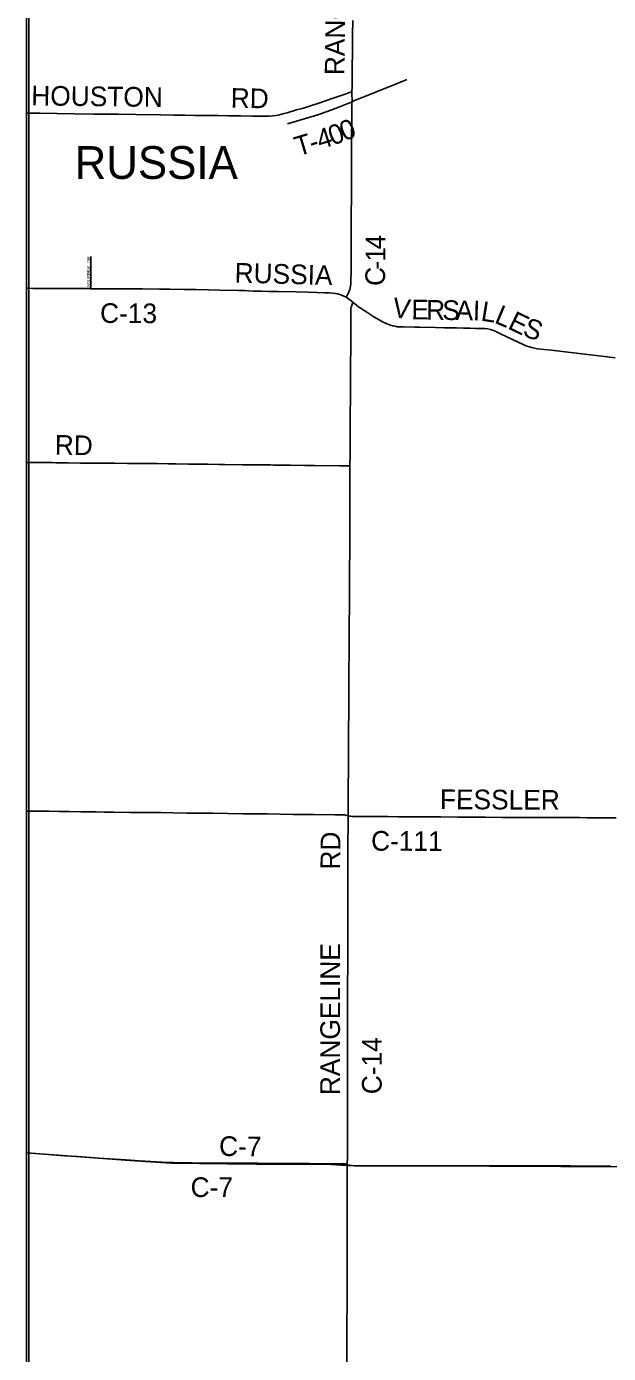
# Model space of a CAD drawing. Extents: x -87 to 2145, y -2128 to 440.
# Drawn here: x 90.3 to 134.7, y -467.2 to -365.9 of the extents above; entities that cross this region are included whole.
import ezdxf

# ---------------------------------------------------------------- set-up
doc = ezdxf.new("R2010")
doc.units = 0
for name, color, linetype in [('GM_X_Adjacent_County', 7, 'Continuous'), ('GM_X_City_Street', 7, 'Continuous'), ('GM_X_City_Street_Text', 7, 'Continuous'), ('GM_X_Corporation_Text', 7, 'Continuous'), ('GM_X_County', 7, 'Continuous'), ('GM_X_County_Road', 7, 'Continuous'), ('GM_X_County_Road_Text', 7, 'Continuous'), ('GM_X_Township', 7, 'Continuous'), ('GM_X_Township_Road', 7, 'Continuous'), ('GM_X_Township_Road_Text', 7, 'Continuous'), ('SH_Border', 7, 'Continuous')]:
    doc.layers.add(name, color=color, linetype=linetype)

msp = doc.modelspace()

# ---------------------------------------------------------------- linework, layer by layer
at = {"layer": 'GM_X_Adjacent_County'}
for points in [[(90.33, -234.66), (90.33, -451.87), (98.23, -452.45), (101.35, -452.66), (107.81, -452.73), (113.2, -452.73), (114.73, -452.82), (141.98, -452.95), (161.81, -452.99), (181.93, -453.06), (195.32, -453.12), (208.54, -453.17), (221.67, -453.23)], [(221.67, -453.23), (208.54, -453.17), (195.32, -453.12), (181.93, -453.06), (161.81, -452.99), (141.98, -452.95), (114.73, -452.82), (113.2, -452.73), (107.81, -452.73), (101.35, -452.66), (98.23, -452.45), (90.33, -451.87), (90.33, -655.29)]]:
    msp.add_lwpolyline(points, dxfattribs=at)
at = {"layer": 'GM_X_City_Street'}
for points in [[(95.21, -385.95), (95.22, -385.73), (95.22, -385.53), (95.23, -384.58), (95.24, -383.5)], [(94.91, -385.94), (95.21, -385.95)], [(95.21, -385.95), (95.73, -385.95), (95.84, -385.95), (95.91, -385.95)]]:
    msp.add_lwpolyline(points, dxfattribs=at)
at = {"layer": 'GM_X_County'}
for points in [[(90.33, -234.66), (90.33, -451.87), (98.23, -452.45), (101.35, -452.66), (107.81, -452.73), (113.2, -452.73), (114.73, -452.82), (141.98, -452.95), (161.81, -452.99), (181.93, -453.06), (195.32, -453.12), (208.54, -453.17), (221.67, -453.23)], [(221.67, -453.23), (208.54, -453.17), (195.32, -453.12), (181.93, -453.06), (161.81, -452.99), (141.98, -452.95), (114.73, -452.82), (113.2, -452.73), (107.81, -452.73), (101.35, -452.66), (98.23, -452.45), (90.33, -451.87), (90.33, -655.29)]]:
    msp.add_lwpolyline(points, dxfattribs=at)
at = {"layer": 'GM_X_County_Road'}
for points in [[(115.14, -370.92), (115.15, -370.56), (115.15, -369.99), (115.17, -369.05), (115.18, -367.91), (115.19, -366.59), (115.2, -365.49)], [(115.15, -371.68), (115.34, -371.6), (115.54, -371.51), (116.04, -371.31), (118.03, -370.51), (119.29, -370), (119.32, -369.99)], [(115.15, -371.68), (115.15, -371.53), (115.15, -371.41), (115.14, -371.25), (115.14, -370.94), (115.14, -370.92)], [(114.69, -386.6), (114.88, -386.26), (114.94, -386.14), (114.98, -386.01), (115.01, -385.88), (115.03, -385.75), (115.05, -385.57), (115.07, -385.27), (115.08, -384.75), (115.09, -383.37), (115.09, -382.34), (115.09, -381.7), (115.09, -380.78), (115.09, -379.98), (115.1, -379.24), (115.1, -378.17), (115.11, -377.65), (115.11, -376.33), (115.12, -374.92), (115.12, -374.15), (115.13, -373.32), (115.14, -372.48), (115.14, -372.15), (115.14, -371.91), (115.14, -371.78), (115.15, -371.68)], [(90.33, -385.91), (90.47, -385.91), (90.81, -385.92), (91.11, -385.93), (92.12, -385.93), (93.17, -385.94), (94.78, -385.94), (94.91, -385.94)], [(95.91, -385.95), (96.3, -385.96)], [(96.3, -385.96), (97.46, -385.95), (98.45, -385.96), (99.17, -385.96), (100.46, -385.97), (101.25, -385.98), (102.38, -386), (103.27, -386.01), (104.21, -386.03), (105.04, -386.05), (106.52, -386.08), (106.96, -386.09), (107.62, -386.12), (108.26, -386.13), (108.77, -386.15), (109.52, -386.17), (110.88, -386.19), (111.77, -386.22), (112.47, -386.23), (113.05, -386.25), (113.41, -386.26), (113.69, -386.28), (113.89, -386.31), (114.05, -386.34), (114.21, -386.38), (114.35, -386.43), (114.52, -386.51), (114.69, -386.6)], [(114.69, -386.6), (114.88, -386.72), (115.09, -386.86), (115.2, -386.96)], [(114.99, -399.45), (115, -398.62), (115.01, -397.52), (115.01, -396.76), (115.01, -395.86), (115.03, -393.88), (115.04, -392.91), (115.04, -391.71), (115.05, -390.48), (115.05, -388.79), (115.05, -387.81), (115.05, -387.6), (115.07, -387.45), (115.09, -387.34), (115.15, -387.14), (115.2, -386.96)], [(115.2, -386.96), (115.5, -387.19), (115.68, -387.34), (115.81, -387.44), (115.94, -387.53), (116.19, -387.69), (116.82, -388.08), (117.21, -388.32), (117.48, -388.47), (117.69, -388.57), (117.89, -388.66), (118.08, -388.72), (118.25, -388.77), (118.43, -388.81), (118.59, -388.84), (118.74, -388.85), (119.07, -388.86), (119.94, -388.87), (120.32, -388.88), (121.51, -388.91), (122.19, -388.93), (123.12, -388.94), (123.64, -388.95), (124.14, -388.96), (124.56, -388.97), (125.01, -388.97), (125.28, -388.99), (125.48, -389.01), (125.7, -389.06), (125.85, -389.11), (126.01, -389.16), (126.22, -389.25), (126.48, -389.38), (127.38, -389.82), (127.87, -390.06), (128.21, -390.21), (128.47, -390.32), (128.69, -390.39), (128.86, -390.44), (129.06, -390.48), (129.3, -390.52), (130.35, -390.64), (131.4, -390.77), (132.48, -390.89), (134.4, -391.12), (135.22, -391.21)], [(114.86, -426.15), (114.86, -425.34), (114.86, -423.65), (114.87, -422.88), (114.88, -421.96), (114.87, -420.51), (114.88, -419.43), (114.9, -418.35), (114.9, -417.48), (114.9, -415.79), (114.91, -414.81), (114.92, -413.95), (114.92, -412.77), (114.93, -412.33), (114.94, -411.18), (114.95, -410.49), (114.95, -410), (114.96, -409.21), (114.96, -407.15), (114.97, -406.13), (114.97, -405.26), (114.97, -404.46), (114.97, -403.95), (114.97, -403.6), (114.97, -403.46), (114.98, -402.55), (114.99, -401.21), (114.99, -400.08), (114.99, -399.45)], [(114.79, -452.75), (114.79, -452.58), (114.8, -452.35), (114.8, -450.55), (114.81, -449), (114.81, -447.91), (114.81, -446.56), (114.81, -445.92), (114.81, -445.26), (114.81, -444.2), (114.81, -443.36), (114.81, -442.36), (114.81, -440.85), (114.81, -440.11), (114.81, -438.7), (114.82, -437.92), (114.82, -437.42), (114.82, -436.78), (114.83, -435.65), (114.82, -435.08), (114.82, -434.49), (114.83, -433.88), (114.82, -433.31), (114.83, -432.7), (114.84, -431.32), (114.84, -430.52), (114.84, -429.8), (114.84, -428.76), (114.84, -427.89), (114.85, -427.26), (114.85, -426.65), (114.86, -426.15)], [(114.86, -426.15), (114.96, -426.17), (115.05, -426.19), (115.16, -426.2), (116.21, -426.21), (117.03, -426.21), (117.88, -426.21), (118.7, -426.22), (120.44, -426.23), (121.93, -426.24), (123.23, -426.25), (123.9, -426.25), (125.34, -426.26), (126.59, -426.27), (127.38, -426.27), (128.07, -426.27), (129.18, -426.28), (130.35, -426.29), (131.44, -426.29), (132.51, -426.29), (133.09, -426.3), (135.3, -426.31)], [(90.33, -451.87), (91.65, -451.96), (93.25, -452.08), (94.2, -452.14), (95.87, -452.26), (96.65, -452.31), (97.9, -452.4), (98.95, -452.47), (99.81, -452.52), (101.04, -452.59), (101.52, -452.61), (102.19, -452.62), (102.9, -452.63), (103.72, -452.64), (105.19, -452.64), (106.49, -452.65), (107.13, -452.65), (107.96, -452.66), (108.98, -452.67), (110.92, -452.68), (111.87, -452.68), (113.13, -452.69), (114.08, -452.7), (114.31, -452.7), (114.51, -452.71), (114.6, -452.71), (114.68, -452.72), (114.77, -452.75), (114.79, -452.75)], [(90.33, -451.87), (91.65, -451.96), (93.25, -452.08), (94.2, -452.14), (95.87, -452.26), (96.65, -452.31), (97.9, -452.4), (98.95, -452.47), (99.81, -452.52), (101.04, -452.59), (101.52, -452.61), (102.19, -452.62), (102.9, -452.63), (103.72, -452.64), (105.19, -452.64), (106.49, -452.65), (107.13, -452.65), (107.96, -452.66), (108.98, -452.67), (110.92, -452.68), (111.87, -452.68), (113.13, -452.69), (114.08, -452.7), (114.31, -452.7), (114.51, -452.71), (114.6, -452.71), (114.68, -452.72), (114.77, -452.75), (114.79, -452.75)], [(114.72, -479.74), (114.71, -479.17), (114.72, -478.05), (114.73, -475.72), (114.73, -474.36), (114.73, -471.21), (114.75, -468.13), (114.76, -465.27), (114.77, -462.99), (114.77, -461.29), (114.77, -460.15), (114.77, -458.66), (114.78, -456.76), (114.79, -455.36), (114.79, -453.81), (114.79, -452.75)], [(114.79, -452.75), (114.86, -452.79), (114.91, -452.8), (114.96, -452.81), (114.98, -452.81), (115.1, -452.82), (115.34, -452.84), (115.51, -452.84), (116.11, -452.84), (116.85, -452.84), (117.54, -452.85), (117.92, -452.84), (118.46, -452.84), (119.58, -452.85), (120.95, -452.85), (121.41, -452.85), (122.1, -452.85), (122.77, -452.85), (123.35, -452.86), (124.4, -452.85), (125.17, -452.85), (125.94, -452.85), (127.22, -452.85), (127.97, -452.85), (129.35, -452.85), (129.88, -452.85), (130.45, -452.85), (131.04, -452.85), (131.83, -452.86), (132.78, -452.87), (133.71, -452.88), (134.14, -452.88), (134.89, -452.87)], [(114.79, -452.75), (114.86, -452.79), (114.91, -452.8), (114.96, -452.81), (114.98, -452.81), (115.1, -452.82), (115.34, -452.84), (115.51, -452.84), (116.11, -452.84), (116.85, -452.84), (117.54, -452.85), (117.92, -452.84), (118.46, -452.84), (119.58, -452.85), (120.95, -452.85), (121.41, -452.85), (122.1, -452.85), (122.77, -452.85), (123.35, -452.86), (124.4, -452.85), (125.17, -452.85), (125.94, -452.85), (127.22, -452.85), (127.97, -452.85), (129.35, -452.85), (129.88, -452.85), (130.45, -452.85), (131.04, -452.85), (131.83, -452.86), (132.78, -452.87), (133.71, -452.88), (134.14, -452.88), (134.89, -452.87)]]:
    msp.add_lwpolyline(points, dxfattribs=at)
at = {"layer": 'GM_X_Township'}
for points in [[(92.09, -319.55), (90.33, -319.52), (90.33, -451.87), (98.23, -452.45), (101.35, -452.66), (107.81, -452.73), (113.2, -452.73), (114.73, -452.82), (141.98, -452.95), (161.81, -452.99), (181.93, -453.06), (195.32, -453.12), (208.54, -453.17), (221.67, -453.23), (221.96, -453.23), (221.93, -449.63)], [(195.19, -479.26), (195.32, -453.12), (181.93, -453.06), (161.81, -452.99), (141.98, -452.95), (114.73, -452.82), (113.2, -452.73), (107.81, -452.73), (101.35, -452.66), (98.23, -452.45), (90.33, -451.87), (90.33, -638.91)]]:
    msp.add_lwpolyline(points, dxfattribs=at)
at = {"layer": 'GM_X_Township_Road'}
for points in [[(90.33, -372.55), (90.43, -372.55), (91.35, -372.56), (92.63, -372.58), (93.96, -372.6), (95.43, -372.62), (96.43, -372.63), (97.35, -372.64), (98.65, -372.66), (100.54, -372.68), (101.55, -372.7), (102.39, -372.71), (103.19, -372.72), (104.13, -372.72), (104.92, -372.73), (105.74, -372.75), (106.67, -372.76), (107.57, -372.78), (108.46, -372.79), (108.82, -372.79), (109.08, -372.77), (109.36, -372.73), (109.61, -372.68), (109.88, -372.61), (110.2, -372.52), (110.91, -372.31), (111.44, -372.16), (112.06, -371.97), (112.63, -371.78), (113.71, -371.42), (114.17, -371.25), (114.62, -371.1), (114.95, -370.99), (115.14, -370.92)], [(110.24, -373.38), (112.55, -372.68), (113.81, -372.23), (114.31, -372.02), (114.69, -371.87), (114.91, -371.78), (115.15, -371.68)], [(90.33, -399.2), (91.55, -399.2), (92.28, -399.21), (92.57, -399.22), (93.5, -399.23), (94.44, -399.24), (94.98, -399.24), (95.54, -399.25), (96.13, -399.26), (96.57, -399.26), (97.03, -399.26), (98.03, -399.27), (98.72, -399.27), (100.31, -399.29), (101.13, -399.3), (101.69, -399.31), (102.67, -399.32), (103.2, -399.32), (104.15, -399.33), (104.97, -399.35), (105.43, -399.35), (106.79, -399.37), (107.89, -399.38), (108.69, -399.39), (108.92, -399.39), (109.15, -399.4), (109.45, -399.4), (110.45, -399.41), (111.55, -399.42), (112.04, -399.43), (112.28, -399.43), (114.22, -399.45), (114.69, -399.45), (114.86, -399.45), (114.99, -399.45)], [(90.33, -425.8), (91.17, -425.8), (92.02, -425.81), (92.84, -425.83), (93.56, -425.83), (94.46, -425.84), (95.63, -425.86), (96.28, -425.87), (97, -425.88), (98.2, -425.89), (98.86, -425.9), (99.37, -425.9), (99.83, -425.9), (100.6, -425.91), (101.48, -425.93), (102.58, -425.94), (103.45, -425.95), (104.52, -425.96), (105.67, -425.97), (106.85, -425.99), (107.8, -426), (108.68, -426.01), (109.68, -426.02), (110.67, -426.04), (112.24, -426.06), (113.85, -426.09), (114.58, -426.09), (114.66, -426.1), (114.76, -426.12), (114.86, -426.15)]]:
    msp.add_lwpolyline(points, dxfattribs=at)
at = {"layer": 'SH_Border'}
for points in [[(90.33, -234.78), (90.33, -654.78), (90.51, -654.78), (90.51, -234.78)], [(342.13, -654.78), (342.13, -234.78), (90.51, -234.78), (90.51, -654.78)]]:
    msp.add_lwpolyline(points, close=True, dxfattribs=at)

# ---------------------------------------------------------------- texts
at = {"layer": 'GM_X_City_Street_Text'}
for s, rotation, p in [('DR', 90, (95.2, -383.97)), ('I', 88.492, (95.18, -384.61)), ('R', 89.6965, (95.18, -384.8)), ('A', 87.4858, (95.18, -384.5)), ('L', 87.39, (95.19, -384.28)), ('T', 89.9764, (95.18, -384.98)), ('S', 89.9863, (95.18, -385.16)), ('U', 89.9891, (95.18, -385.38)), ('D', 89.9891, (95.18, -385.6)), ('N', 89.987, (95.18, -385.82)), ('I', 89.9781, (95.18, -385.93))]:
    msp.add_text(s, height=0.25, rotation=rotation, dxfattribs=at).set_placement(p)
at = {"layer": 'GM_X_Corporation_Text'}
msp.add_text('RUSSIA', height=2.5, rotation=0, dxfattribs=at).set_placement((93.99, -377.57))
at = {"layer": 'GM_X_County_Road_Text'}
for s, rotation, p in [('RANGELINE', 89.4032, (114.57, -369.66)), ('4', 89.6157, (117.69, -382.95)), ('1', 89.5847, (117.69, -383.88)), ('RUSSIA', 358.4567, (106.18, -385.47)), ('C', 88.626, (117.65, -385.75)), ('-', 89.4935, (117.68, -384.5)), ('V', 352.6378, (118.17, -388.1)), ('C-13', 359.6556, (95.93, -388.55)), ('E', 359.3575, (119.67, -388.28)), ('R', 358.9969, (120.79, -388.3)), ('S', 358.995, (122.02, -388.32)), ('A', 358.9563, (123.04, -388.34)), ('I', 358.5011, (124.35, -388.36)), ('L', 350.9129, (124.92, -388.37)), ('L', 337.2527, (125.93, -388.52)), ('E', 334.0847, (126.95, -388.95)), ('S', 338.6692, (128.08, -389.49)), ('FESSLER', 359.6722, (121.85, -425.64)), ('RD', 89.5097, (114.24, -430.26)), ('C-111', 359.7288, (116.6, -428.81)), ('RANGELINE', 89.8786, (114.22, -447.46)), ('C-14', 90, (117.41, -447.39)), ('C-7', 359.1542, (105, -452.09)), ('C-7', 0, (102.84, -455.23))]:
    msp.add_text(s, height=1.5, rotation=rotation, dxfattribs=at).set_placement(p)
at = {"layer": 'GM_X_Township_Road_Text'}
for s, rotation, p in [('HOUSTON', 359.2974, (90.68, -371.96)), ('RD', 359.0104, (105.89, -372.14)), ('0', 20.0113, (113.66, -375.04)), ('0', 20.9205, (114.55, -374.71)), ('T', 16.7766, (111.03, -375.86)), ('4', 17.919, (112.72, -375.34)), ('-', 17.053, (112.11, -375.53)), ('RD', 359.0258, (92.47, -398.6))]:
    msp.add_text(s, height=1.5, rotation=rotation, dxfattribs=at).set_placement(p)

doc.saveas('drawing.dxf')
